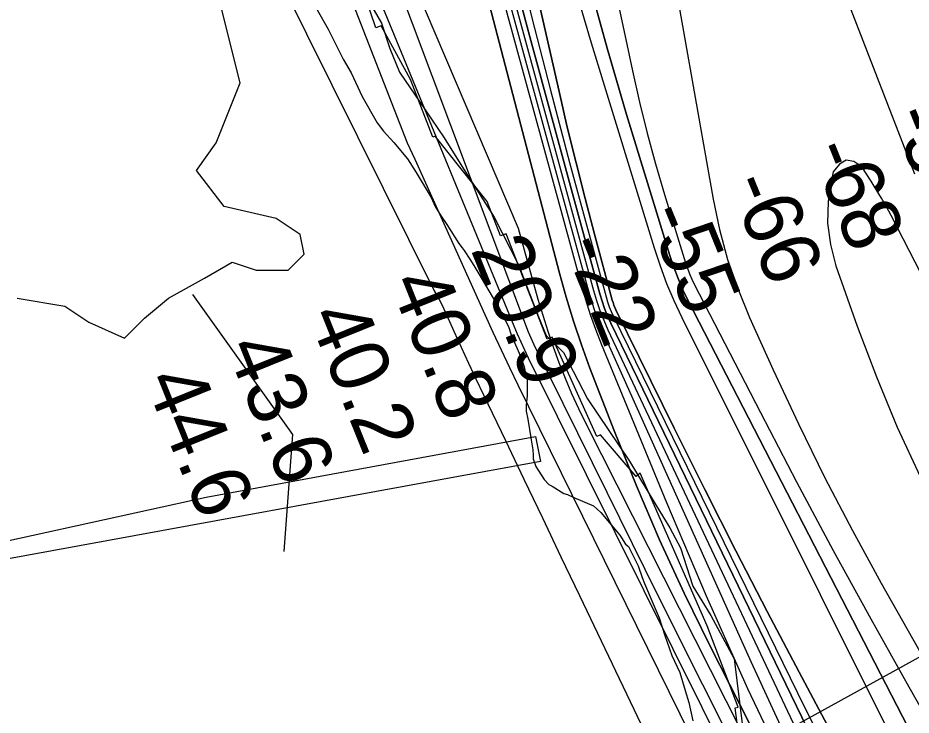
# Model space of a CAD drawing. Extents: x 3279314 to 3317160, y 734079 to 759431.
# Drawn here: x 3284746 to 3285762, y 755360 to 756153 of the extents above; entities that cross this region are included whole.
import ezdxf

# ---------------------------------------------------------------- set-up
doc = ezdxf.new("R2010")
doc.units = 0
for name, color, linetype in [('V-RIVR-EDGE', 7, 'Continuous'), ('V-RIVR-RANG', 7, 'Continuous'), ('V-RRAP-RVMT', 7, 'Continuous'), ('V-SITE-VEGE', 7, 'Continuous'), ('V-TOPO-DPTH', 7, 'Continuous'), ('V-TOPO-MAJR', 7, 'Continuous'), ('V-TOPO-MINR', 7, 'Continuous'), ('V-TOPO-SHOR', 7, 'Continuous'), ('V-TOPO-WATR', 7, 'Continuous')]:
    doc.layers.add(name, color=color, linetype=linetype)

msp = doc.modelspace()

# ---------------------------------------------------------------- linework, layer by layer
at = {"layer": 'V-RIVR-EDGE'}
msp.add_lwpolyline([(3285146.8, 756168.9), (3285159.3, 756147.5), (3285168.8, 756118.4), (3285180, 756091.8), (3285209.1, 756048.7), (3285230.7, 756016.9), (3285250.6, 755984.7), (3285287.4, 755926.8), (3285315.1, 755872.4), (3285338, 755813.3), (3285346.6, 755791.9), (3285366.6, 755772.8), (3285393.9, 755720.1), (3285441.5, 755649.1), (3285471.8, 755598.6), (3285487.4, 755573.4), (3285499.5, 755550.7), (3285513.7, 755506.8), (3285534.1, 755473.7), (3285560.5, 755424.1), (3285569.8, 755350.2)], dxfattribs=at)
at = {"layer": 'V-RIVR-RANG'}
msp.add_line((3285417, 755231.3), (3286152.8, 755636.5), dxfattribs=at)
at = {"layer": 'V-RRAP-RVMT'}
for p, q in [((3285681, 756194.7), (3285766, 755976.1)), ((3285152.9, 756142.2), (3285138, 756186.3)), ((3285159, 756144.4), (3285152.9, 756142.2)), ((3285192.4, 756083.3), (3285159, 756144.4)), ((3285217.6, 756017.8), (3285192.4, 756083.3)), ((3285220.5, 756018.9), (3285217.6, 756017.8)), ((3285279.5, 755944.6), (3285220.5, 756018.9)), ((3285294.9, 755905.3), (3285279.5, 755944.6)), ((3285301.2, 755907.7), (3285294.9, 755905.3)), ((3285347.7, 755787.9), (3285301.2, 755907.7)), ((3285353.5, 755790.2), (3285347.7, 755787.9)), ((3285404.4, 755677.2), (3285353.5, 755790.2)), ((3285408.6, 755679.1), (3285404.4, 755677.2)), ((3285449.3, 755631.8), (3285408.6, 755679.1)), ((3285453.7, 755635.6), (3285449.3, 755631.8)), ((3285530.1, 755461.9), (3285453.7, 755635.6)), ((3285565.3, 755369.1), (3285530.1, 755461.9)), ((3285561.7, 755368.5), (3285565.3, 755369.1)), ((3285588.5, 755172.9), (3285561.7, 755368.5))]:
    msp.add_line(p, q, dxfattribs=at)
at = {"layer": 'V-SITE-VEGE'}
for p, q in [((3284998.7, 756079.5), (3284971.4, 756188.4)), ((3285086.2, 756162.4), (3285098.7, 756140.5)), ((3285098.7, 756140.5), (3285107.2, 756123.7)), ((3285107.2, 756123.7), (3285115.8, 756106.3)), ((3285115.8, 756106.3), (3285124.9, 756090.8)), ((3285124.9, 756090.8), (3285137.4, 756063.8)), ((3284971.4, 756011.4), (3284998.7, 756079.5)), ((3285137.4, 756063.8), (3285154.5, 756034.1)), ((3285154.5, 756034.1), (3285161.7, 756024.5)), ((3285161.7, 756024.5), (3285173.4, 756011.6)), ((3284948.8, 755979.7), (3284971.4, 756011.4)), ((3285173.4, 756011.6), (3285189.1, 755992.9)), ((3285189.1, 755992.9), (3285198.9, 755977.5)), ((3284980.5, 755938.8), (3284948.8, 755979.7)), ((3285198.9, 755977.5), (3285216, 755949.1)), ((3285216, 755949.1), (3285220.6, 755938.8)), ((3285039.5, 755925.2), (3284980.5, 755938.8)), ((3285220.6, 755938.8), (3285227.1, 755927.8)), ((3285066.7, 755907.1), (3285039.5, 755925.2)), ((3285227.1, 755927.8), (3285233.7, 755918.2)), ((3285233.7, 755918.2), (3285247.4, 755896.9)), ((3285071.2, 755884.4), (3285066.7, 755907.1)), ((3285247.4, 755896.9), (3285251.3, 755891.8)), ((3285251.3, 755891.8), (3285253.3, 755888.6)), ((3285053.1, 755866.2), (3285071.2, 755884.4)), ((3285253.3, 755888.6), (3285259.9, 755878.9)), ((3285259.9, 755878.9), (3285264.4, 755871.8)), ((3284957.8, 755857.1), (3284989.6, 755875.3)), ((3284989.6, 755875.3), (3285016.8, 755866.2)), ((3285264.4, 755871.8), (3285270.3, 755862.2)), ((3285016.8, 755866.2), (3285053.1, 755866.2)), ((3285270.3, 755862.2), (3285285.4, 755836.4)), ((3284917, 755834.4), (3284957.8, 755857.1)), ((3284744.7, 755834.4), (3284799.1, 755825.4)), ((3284889.8, 755811.8), (3284917, 755834.4)), ((3285285.4, 755836.4), (3285292, 755825.4)), ((3284799.1, 755825.4), (3284826.3, 755807.2)), ((3285292, 755825.4), (3285303.8, 755802.2)), ((3284867.1, 755789.1), (3284889.8, 755811.8)), ((3284826.3, 755807.2), (3284867.1, 755789.1)), ((3285303.8, 755802.2), (3285306.4, 755793.8)), ((3285306.4, 755793.8), (3285311.7, 755781.6)), ((3285311.7, 755781.6), (3285317.6, 755768.7)), ((3285317.6, 755768.7), (3285318.3, 755766.1)), ((3285318.3, 755766.1), (3285321.6, 755756.4)), ((3285321.6, 755756.4), (3285323, 755750.6)), ((3285323, 755750.6), (3285323.6, 755746)), ((3285323.6, 755746), (3285325, 755741.5)), ((3285325, 755741.5), (3285325.1, 755723.4)), ((3285325.1, 755723.4), (3285323.9, 755713)), ((3285323.9, 755713), (3285323.9, 755705.9)), ((3285323.9, 755705.9), (3285325.9, 755696.9)), ((3285325.9, 755696.9), (3285329.3, 755675.5)), ((3285329.3, 755675.5), (3285331.4, 755662)), ((3285331.4, 755662), (3285332.1, 755656.1)), ((3285332.1, 755656.1), (3285332.1, 755651.6)), ((3285332.1, 755651.6), (3285334.8, 755643.2)), ((3285334.8, 755643.2), (3285344.6, 755628.4)), ((3285344.6, 755628.4), (3285349.8, 755622.6)), ((3285349.8, 755622.6), (3285353.7, 755620.7)), ((3285353.7, 755620.7), (3285366.7, 755612.4)), ((3285366.7, 755612.4), (3285371.2, 755611.1)), ((3285371.2, 755611.1), (3285378.4, 755607.9)), ((3285378.4, 755607.9), (3285400.5, 755598.4)), ((3285400.5, 755598.4), (3285408.9, 755590.7)), ((3285408.9, 755590.7), (3285420.7, 755576.5)), ((3285420.7, 755576.5), (3285430.5, 755565)), ((3285430.5, 755565), (3285437, 755554.6)), ((3285437, 755554.6), (3285440.3, 755552.1)), ((3285440.3, 755552.1), (3285451.5, 755530.2)), ((3285451.5, 755530.2), (3285456.1, 755516.6)), ((3285456.1, 755516.6), (3285458.7, 755510.1)), ((3285458.7, 755510.1), (3285468.6, 755486.9)), ((3285468.6, 755486.9), (3285475.2, 755470.8)), ((3285475.2, 755470.8), (3285481.8, 755450.8)), ((3285481.8, 755450.8), (3285489.8, 755428.2)), ((3285489.8, 755428.2), (3285499, 755408.8)), ((3285499, 755408.8), (3285505, 755388.2)), ((3285505, 755388.2), (3285508.9, 755374.6)), ((3285508.9, 755374.6), (3285513.6, 755353.9))]:
    msp.add_line(p, q, dxfattribs=at)
at = {"layer": 'V-TOPO-DPTH'}
for p, q in [((3285416, 756118.9), (3285395.1, 756194.9)), ((3285416, 756118.9), (3285395.1, 756194.9)), ((3285438.2, 756043.3), (3285416, 756118.9)), ((3285438.2, 756043.3), (3285416, 756118.9)), ((3285487.5, 755883.1), (3285438.2, 756043.3)), ((3285487.5, 755883.1), (3285438.2, 756043.3)), ((3285491.9, 755869.9), (3285487.5, 755883.1)), ((3285491.9, 755869.9), (3285487.5, 755883.1)), ((3285496.8, 755856.9), (3285491.9, 755869.9)), ((3285496.8, 755856.9), (3285491.9, 755869.9)), ((3285502.4, 755844.1), (3285496.8, 755856.9)), ((3285502.4, 755844.1), (3285496.8, 755856.9)), ((3285508.5, 755831.6), (3285502.4, 755844.1)), ((3285508.5, 755831.6), (3285502.4, 755844.1)), ((3285758.1, 755346.9), (3285508.5, 755831.6)), ((3285758.1, 755346.9), (3285508.5, 755831.6))]:
    msp.add_line(p, q, dxfattribs=at)
for points in [[(3285913.4, 754884.8), (3285634.5, 755409), (3285598.2, 755478), (3285562.4, 755547.3), (3285527.2, 755616.9), (3285492.4, 755686.7), (3285426.2, 755821.3), (3285425, 755824), (3285423.8, 755826.7), (3285422.9, 755829.5), (3285422, 755832.4), (3285401.7, 755907.4), (3285391, 755947.8), (3285380.7, 755988.3), (3285370.8, 756029), (3285361.4, 756069.7), (3285317.7, 756262.9), (3285286.9, 756400.3), (3285256.2, 756537.7), (3285225.8, 756675.2), (3285195.6, 756812.8), (3285136.8, 757082)], [(3285913.4, 754884.8), (3285634.5, 755409), (3285598.2, 755478), (3285562.4, 755547.3), (3285527.2, 755616.9), (3285492.4, 755686.7), (3285426.2, 755821.3), (3285425, 755824), (3285423.8, 755826.7), (3285422.9, 755829.5), (3285422, 755832.4), (3285401.7, 755907.4), (3285391, 755947.8), (3285380.7, 755988.3), (3285370.8, 756029), (3285361.4, 756069.7), (3285317.7, 756262.9), (3285286.9, 756400.3), (3285256.2, 756537.7), (3285225.8, 756675.2), (3285195.6, 756812.8), (3285136.8, 757082)], [(3285117.1, 757050.8), (3285149.1, 756896.1), (3285168.8, 756802.4), (3285188.9, 756708.8), (3285209.6, 756615.3), (3285230.6, 756521.9), (3285232.1, 756515.7), (3285254.7, 756419.4), (3285278.1, 756323.3), (3285302.8, 756227.5), (3285328.2, 756131.9), (3285407.8, 755839.5), (3285410.4, 755831), (3285413.3, 755822.6), (3285416.6, 755814.3), (3285420.3, 755806.2), (3285867.1, 754884.5)], [(3285867.1, 754884.5), (3285420.3, 755806.2), (3285416.6, 755814.3), (3285413.3, 755822.6), (3285410.4, 755831), (3285407.8, 755839.5), (3285328.2, 756131.9), (3285302.8, 756227.5), (3285278.1, 756323.3), (3285254.7, 756419.4), (3285232.1, 756515.7), (3285230.6, 756521.9), (3285209.6, 756615.3), (3285188.9, 756708.8), (3285168.8, 756802.4), (3285149.1, 756896.1), (3285117.1, 757050.8)], [(3286018.1, 754505.5), (3285995.9, 754546.8), (3285973.7, 754588), (3285951.4, 754629.3), (3285929, 754670.5), (3285879.6, 754761.2), (3285868.1, 754782.5), (3285856.7, 754803.8), (3285845.5, 754825.3), (3285834.5, 754846.8), (3285533.3, 755438.7), (3285503.9, 755498.8), (3285475.7, 755559.5), (3285449.4, 755621), (3285424.4, 755683), (3285396.6, 755755), (3285386.9, 755781.6), (3285377.7, 755808.5), (3285369.5, 755835.7), (3285361.8, 755863), (3285059.4, 757021.6)], [(3285100.5, 756977.9), (3285110.6, 756928.7), (3285120.9, 756879.6), (3285131.7, 756830.6), (3285142.8, 756781.7), (3285144.1, 756775.8), (3285156.4, 756724), (3285169.1, 756672.4), (3285182.4, 756620.9), (3285196.1, 756569.5), (3285393.6, 755846.6), (3285397.8, 755832.4), (3285402.5, 755818.3), (3285407.8, 755804.5), (3285413.6, 755790.8), (3285579.7, 755421.2), (3285626.5, 755319.2)], [(3285100.5, 756977.9), (3285110.6, 756928.7), (3285120.9, 756879.6), (3285131.7, 756830.6), (3285142.8, 756781.7), (3285144.1, 756775.8), (3285156.4, 756724), (3285169.1, 756672.4), (3285182.4, 756620.9), (3285196.1, 756569.5), (3285393.6, 755846.6), (3285397.8, 755832.4), (3285402.5, 755818.3), (3285407.8, 755804.5), (3285413.6, 755790.8), (3285579.7, 755421.2), (3285626.5, 755319.2)], [(3285194.9, 756978.3), (3285205.4, 756918.5), (3285216.4, 756858.8), (3285228.5, 756799.3), (3285241.1, 756739.9), (3285269.3, 756612.3), (3285298, 756489.6), (3285328.6, 756367.4), (3285362.2, 756245.9), (3285397.8, 756125), (3285469.5, 755891.6), (3285476.3, 755871.4), (3285483.7, 755851.4), (3285492.1, 755831.9), (3285501.1, 755812.6), (3285815.9, 755182.3)], [(3285194.9, 756978.3), (3285205.4, 756918.5), (3285216.4, 756858.8), (3285228.5, 756799.3), (3285241.1, 756739.9), (3285269.3, 756612.3), (3285298, 756489.6), (3285328.6, 756367.4), (3285362.2, 756245.9), (3285397.8, 756125), (3285469.5, 755891.6), (3285476.3, 755871.4), (3285483.7, 755851.4), (3285492.1, 755831.9), (3285501.1, 755812.6), (3285815.9, 755182.3)]]:
    msp.add_lwpolyline(points, dxfattribs=at)
at = {"layer": 'V-TOPO-MAJR'}
for points in [[(3285271.8, 757124.4), (3285415.4, 756235.4), (3285422.6, 756199.8), (3285429.9, 756164.2), (3285437.3, 756128.6), (3285444.9, 756093), (3285452.9, 756057.6), (3285461.6, 756022.4), (3285471.2, 755987.3), (3285481.4, 755952.5), (3285505.4, 755874.7), (3285507.5, 755868.5), (3285509.8, 755862.3), (3285512.4, 755856.2), (3285515.3, 755850.3), (3285590.5, 755704.3), (3285631.6, 755625.7), (3285673.3, 755547.4), (3285716, 755469.7), (3285759.3, 755392.3), (3286005.2, 754959.4)], [(3284824.7, 756985.5), (3285132.8, 756225.4), (3285148.5, 756192.7), (3285163.1, 756159.4), (3285309.9, 755803.2), (3285313.8, 755794), (3285317.8, 755784.8), (3285322.1, 755775.8), (3285326.4, 755766.8), (3285655.6, 755104.7)]]:
    msp.add_lwpolyline(points, dxfattribs=at)
at = {"layer": 'V-TOPO-MINR'}
for p, q in [((3285395.1, 756194.9), (3285416, 756118.9)), ((3285416, 756118.9), (3285438.2, 756043.3)), ((3285438.2, 756043.3), (3285487.5, 755883.1)), ((3285487.5, 755883.1), (3285491.9, 755869.9)), ((3285491.9, 755869.9), (3285496.8, 755856.9)), ((3285496.8, 755856.9), (3285502.4, 755844.1)), ((3285502.4, 755844.1), (3285508.5, 755831.6)), ((3285508.5, 755831.6), (3285758.1, 755346.9))]:
    msp.add_line(p, q, dxfattribs=at)
for points in [[(3285136.8, 757082), (3285195.6, 756812.8), (3285225.8, 756675.2), (3285256.2, 756537.7), (3285286.9, 756400.3), (3285317.7, 756262.9), (3285361.4, 756069.7), (3285370.8, 756029), (3285380.7, 755988.3), (3285391, 755947.8), (3285401.7, 755907.4), (3285422, 755832.4), (3285422.9, 755829.5), (3285423.8, 755826.7), (3285425, 755824), (3285426.2, 755821.3), (3285492.4, 755686.7), (3285527.2, 755616.9), (3285562.4, 755547.3), (3285598.2, 755478), (3285634.5, 755409), (3285913.4, 754884.8)], [(3285127.6, 757067.4), (3285172.6, 756855), (3285197.5, 756739.1), (3285222.7, 756623.3), (3285248.4, 756507.6), (3285274.4, 756391.9), (3285290.9, 756319.3), (3285310.3, 756236.4), (3285330.4, 756153.6), (3285351.5, 756071.1), (3285373.4, 755988.8), (3285414.9, 755836), (3285416.6, 755830.3), (3285418.6, 755824.7), (3285420.8, 755819.2), (3285423.3, 755813.8), (3285632.8, 755385.6), (3285678.2, 755293.8)], [(3285117.1, 757050.8), (3285149.1, 756896.1), (3285168.8, 756802.4), (3285188.9, 756708.8), (3285209.6, 756615.3), (3285230.6, 756521.9), (3285232.1, 756515.7), (3285254.7, 756419.4), (3285278.1, 756323.3), (3285302.8, 756227.5), (3285328.2, 756131.9), (3285407.8, 755839.5), (3285410.4, 755831), (3285413.3, 755822.6), (3285416.6, 755814.3), (3285420.3, 755806.2), (3285867.1, 754884.5)], [(3285105.6, 757032.8), (3285125, 756937), (3285139.8, 756865.6), (3285155, 756794.2), (3285170.7, 756722.9), (3285186.8, 756651.8), (3285188.3, 756645), (3285205.9, 756570.6), (3285224.1, 756496.4), (3285243.1, 756422.3), (3285262.8, 756348.5), (3285400.7, 755843.1), (3285404.1, 755831.7), (3285407.9, 755820.5), (3285412.3, 755809.4), (3285417.1, 755798.6), (3285720.8, 755153.8)], [(3284844, 757017.6), (3285314.7, 755914.1), (3285337.4, 755833.4), (3285342.8, 755815.2), (3285348.5, 755797.1), (3285354.7, 755779.1), (3285361.3, 755761.3), (3285368.3, 755743.6), (3285375.7, 755726.1), (3285383.6, 755708.9), (3285392, 755691.8), (3285816.6, 754851.7), (3285830.8, 754823.9), (3285845.2, 754796.3), (3285859.7, 754768.7), (3285874.5, 754741.2), (3285898.7, 754696.5), (3285913.9, 754668.3), (3285929.1, 754640.1), (3285944.1, 754611.8), (3285959.1, 754583.4), (3285973.8, 754555), (3285988.3, 754526.5), (3286002.5, 754497.8)], [(3285059.4, 757021.6), (3285361.8, 755863), (3285369.5, 755835.7), (3285377.7, 755808.5), (3285386.9, 755781.6), (3285396.6, 755755), (3285424.4, 755683), (3285449.4, 755621), (3285475.7, 755559.5), (3285503.9, 755498.8), (3285533.3, 755438.7), (3285834.5, 754846.8), (3285845.5, 754825.3), (3285856.7, 754803.8), (3285868.1, 754782.5), (3285879.6, 754761.2), (3285929, 754670.5), (3285951.4, 754629.3), (3285973.7, 754588), (3285995.9, 754546.8), (3286018.1, 754505.5)], [(3284834.3, 757001.6), (3285107.9, 756372.7), (3285128.1, 756323.2), (3285326.4, 755796.4), (3285327.8, 755792.9), (3285329.3, 755789.5), (3285330.8, 755786), (3285332.4, 755782.7), (3285415.6, 755614), (3285458.9, 755526.3), (3285502.6, 755438.8), (3285546.5, 755351.4)], [(3285194.9, 756978.3), (3285205.4, 756918.5), (3285216.4, 756858.8), (3285228.5, 756799.3), (3285241.1, 756739.9), (3285269.3, 756612.3), (3285298, 756489.6), (3285328.6, 756367.4), (3285362.2, 756245.9), (3285397.8, 756125), (3285469.5, 755891.6), (3285476.3, 755871.4), (3285483.7, 755851.4), (3285492.1, 755831.9), (3285501.1, 755812.6), (3285815.9, 755182.3)], [(3284815.1, 756969.4), (3285188.4, 756011.2), (3285197.2, 755992.8), (3285276.8, 755815.9), (3285286, 755795.8), (3285295.4, 755775.7), (3285304.9, 755755.8), (3285314.6, 755735.8), (3285572.4, 755212.3), (3285609, 755137.2), (3285645.4, 755062), (3285681.3, 754986.5), (3285716.9, 754910.9), (3285758.1, 754822.6), (3285772.6, 754790.9), (3285786.9, 754759.1), (3285800.8, 754727.1), (3285814.5, 754695), (3285861.5, 754582.4), (3285867.6, 754567.2), (3285873.4, 754551.9), (3285878.8, 754536.4), (3285883.8, 754520.8), (3285888.6, 754505.1)], [(3285086.7, 756965), (3285092.6, 756938.3), (3285098.7, 756911.6), (3285099.5, 756907.8), (3285106.3, 756879.3), (3285113.3, 756850.8), (3285120.7, 756822.4), (3285128.2, 756794.1), (3285386.4, 755850.2), (3285391.5, 755833.1), (3285396.9, 755816.1), (3285403, 755799.3), (3285409.4, 755782.7), (3285483.7, 755602.1), (3285528.9, 755495.8), (3285575.9, 755390.4), (3285625.5, 755286.2)], [(3284708.4, 756930), (3284783.1, 756721.1), (3285219.3, 755842.7), (3285222.2, 755838), (3285225, 755833.1), (3285227.6, 755828.1), (3285230, 755823.1), (3285241.7, 755797), (3285250, 755778.8), (3285258.3, 755760.7), (3285266.8, 755742.7), (3285275.3, 755724.6), (3285300.3, 755672.5), (3285321.3, 755628.5), (3285342.4, 755584.5), (3285363.5, 755540.4), (3285384.5, 755496.4), (3285738.3, 754756.8)], [(3285482.5, 756253.8), (3285536.6, 755947), (3285544, 755912.5), (3285553.1, 755878.6), (3285564.7, 755845.4), (3285578, 755812.7), (3285604.9, 755753.1), (3285633.8, 755691.4), (3285663.7, 755630.3), (3285695.3, 755570.1), (3285728.1, 755510.4), (3286053.3, 754935.7)], [(3285821.8, 755768.5), (3285739.2, 755928.4), (3285733.9, 755938.5), (3285728.3, 755948.4), (3285722.4, 755958.2), (3285716.4, 755967.8), (3285706.1, 755983.8), (3285696.7, 755989.9), (3285688, 755991.7), (3285680.4, 755987.1), (3285673.5, 755978.2), (3285671.3, 755969.2), (3285667.6, 755944.5), (3285666.7, 755920), (3285670.1, 755895.7), (3285676.3, 755871.5), (3285700.7, 755802.8), (3285722.6, 755744.9), (3285746.3, 755687.8), (3285772.4, 755631.8)], [(3284944.4, 755838.8), (3285058, 755679.5), (3285048.4, 755546.4)]]:
    msp.add_lwpolyline(points, dxfattribs=at)
at = {"layer": 'V-TOPO-SHOR'}
msp.add_line((3285340.4, 755648.8), (3284694.3, 755530.5), dxfattribs=at)
msp.add_lwpolyline([(3284697, 755550.4), (3284959.7, 755608.2), (3285334.6, 755677.1), (3285340.3, 755648.8)], dxfattribs=at)
at = {"layer": 'V-TOPO-WATR'}
msp.add_lwpolyline([(3285100.5, 756977.9), (3285110.6, 756928.7), (3285120.9, 756879.6), (3285131.7, 756830.6), (3285142.8, 756781.7), (3285144.1, 756775.8), (3285156.4, 756724), (3285169.1, 756672.4), (3285182.4, 756620.9), (3285196.1, 756569.5), (3285393.6, 755846.6), (3285397.8, 755832.4), (3285402.5, 755818.3), (3285407.8, 755804.5), (3285413.6, 755790.8), (3285579.7, 755421.2), (3285626.5, 755319.2)], dxfattribs=at)

# ---------------------------------------------------------------- texts
at = {"layer": 'V-RIVR-RANG'}
for s, rotation, p in [('-57', 291.9982, (3285738.2, 756042.2)), ('-68', 291.9982, (3285646.1, 756003.1)), ('-66', 291.9982, (3285553.6, 755965)), ('-55', 291.9982, (3285459.6, 755930.9)), ('20.9', 291.9383, (3285260.5, 755890)), ('-22', 291.9982, (3285366.1, 755895.3)), ('40.8', 291.9383, (3285167.9, 755852.2)), ('40.2', 291.9383, (3285075.3, 755814.6)), ('43.6', 291.9383, (3284981.9, 755778.8)), ('44.6', 291.9383, (3284889.3, 755741.2))]:
    msp.add_text(s, height=67, rotation=rotation, dxfattribs=at).set_placement(p)

doc.saveas('drawing.dxf')
